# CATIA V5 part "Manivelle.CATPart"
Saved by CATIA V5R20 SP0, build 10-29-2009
Part number: Manivelle
Bounding box of the stored display mesh (mm): x 0 to 1, y 11.252 to 14.694, z 2.82 to 6.598
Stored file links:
  C:\Users\MATT\Desktop\CATIA_Projet_IAO\CATIA FINAL\Manivelle.CATPart
  C:\Users\MATT\Desktop\CATIA_Projet_IAO\CATIA FINAL\mderemetz.CATProduct
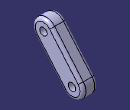
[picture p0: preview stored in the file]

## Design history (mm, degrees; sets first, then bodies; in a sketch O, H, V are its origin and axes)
External parameters (linked from other documents)
  External.AC = 3 mm
Set1
  Plane1 "Plan_Ref": linked copy from another document
  Point1 "A": linked copy from another document
  Point2 "C": linked copy from another document
  Plane2 "Plan_Sec": linked copy from another document
Body1 (main body)
  Sketch1 on Plane1, origin (0, 0, 0), H (0, 1, 0), V (0, 0, 1)
    construction line L1 (12, 5.85) -> (13.9467, 3.5674)
    point P1 (12, 5.85)
    point P2 (13.9467, 3.5674)
    line L2 (12.5706, 6.3367) -> (14.5174, 4.0541)
    line L3 (13.3761, 3.0807) -> (11.4294, 5.3633)
    arc A1 centre (13.9467, 3.5674) radius 0.75 from (14.5174, 4.0541) to (13.3761, 3.0807) cw
    arc A2 centre (12, 5.85) radius 0.75 from (11.4294, 5.3633) to (12.5706, 6.3367) cw
    reference projected point E1 (12, 5.85) from Point1
    reference projected point E2 (13.9467, 3.5674) from Point2
    distance L3 L2 = 1.5 {= 1.5*External.AC /3}
    tangency: A1 L2, A2 L2, A1 L3, A2 L3
    parallelism: L1 L2
    coincidence: P1 E1, P2 E2
  Pad1: profile Sketch1, direction (1, 0, 0), up to Plane2
  Sketch2 on end face of Pad1, origin (1, 12.7334, 4.604), H (0, 1, 0), V (0, 0, 1)
    point P1 (-0.7334, 1.246)
    reference projected point E1 (-0.7334, 1.246) from Point1
    coincidence: P1 E1
  Hole1: placed by Sketch2, at (1, 12, 5.85) direction (-1, 0, 0), diameter 0.5 {= 0.5*External.AC /3}, through (limit type 3)
  Sketch3 on end face of Pad1, origin (1, 14.0739, 3.2043), H (0, 1, 0), V (0, 0, 1)
    point P1 (-0.1272, 0.3632)
    reference projected point E1 (-0.1272, 0.3632) from Point2
    coincidence: P1 E1
  Hole2: placed by Sketch3, at (1, 13.9467, 3.5674) direction (-1, 0, 0), diameter 0.5 {= 0.5*External.AC /3}, through (limit type 3)
  Fillet1: radius 0.2 {= 0.2*External.AC /3}, on edge [end face of Pad1 | face of Pad1 from Sketch1.L3]; edge [start face of Pad1 | face of Pad1 from Sketch1.L3]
